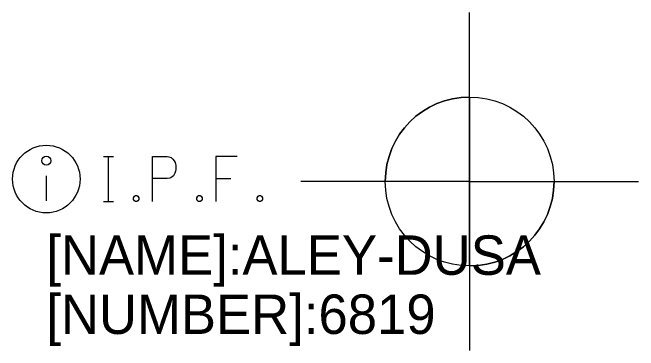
# Model space of a CAD drawing. Extents: x 1386013 to 1389776, y 604170 to 607009.
# Drawn here: x 1389753.55 to 1389775.79, y 606997.38 to 607009.38 of the extents above; entities that cross this region are included whole.
import ezdxf

# ---------------------------------------------------------------- set-up
doc = ezdxf.new("R2010")
doc.units = 0
for name, color, linetype in [('SC_Scratch1', 7, 'Continuous'), ('SH_Text', 7, 'Continuous'), ('SV_X_Mon_Cells_Found_Text', 7, 'Continuous')]:
    doc.layers.add(name, color=color, linetype=linetype)

msp = doc.modelspace()

# ---------------------------------------------------------------- linework, layer by layer
at = {"layer": 'SC_Scratch1'}
msp.add_line((1389754.745, 607003.58), (1389754.745, 607002.697), dxfattribs=at)
for points in [[(1389756.775, 607004.264), (1389757.128, 607004.264)], [(1389756.952, 607002.664), (1389756.952, 607004.264)], [(1389758.517, 607002.664), (1389758.517, 607004.264), (1389759.046, 607004.264), (1389759.101, 607004.251), (1389759.178, 607004.226), (1389759.212, 607004.201), (1389759.244, 607004.176), (1389759.289, 607004.113), (1389759.322, 607004.05), (1389759.344, 607003.949), (1389759.344, 607003.798), (1389759.333, 607003.747), (1389759.311, 607003.672), (1389759.267, 607003.584), (1389759.222, 607003.546), (1389759.189, 607003.52), (1389759.134, 607003.495), (1389759.046, 607003.483), (1389758.517, 607003.483)], [(1389761.526, 607004.264), (1389760.766, 607004.264), (1389760.766, 607002.664)], [(1389760.766, 607003.483), (1389761.306, 607003.483)], [(1389757.911, 607002.878), (1389757.966, 607002.878), (1389757.999, 607002.853), (1389758.032, 607002.802), (1389758.032, 607002.739), (1389757.999, 607002.689), (1389757.966, 607002.664), (1389757.911, 607002.664), (1389757.878, 607002.689), (1389757.845, 607002.739), (1389757.845, 607002.802), (1389757.878, 607002.853), (1389757.911, 607002.878)], [(1389760.159, 607002.878), (1389760.215, 607002.878), (1389760.248, 607002.853), (1389760.281, 607002.802), (1389760.281, 607002.739), (1389760.248, 607002.689), (1389760.215, 607002.664), (1389760.159, 607002.664), (1389760.126, 607002.689), (1389760.093, 607002.739), (1389760.093, 607002.802), (1389760.126, 607002.853), (1389760.159, 607002.878)], [(1389762.309, 607002.878), (1389762.364, 607002.878), (1389762.397, 607002.853), (1389762.43, 607002.802), (1389762.43, 607002.739), (1389762.397, 607002.689), (1389762.364, 607002.664), (1389762.309, 607002.664), (1389762.276, 607002.689), (1389762.243, 607002.739), (1389762.243, 607002.802), (1389762.276, 607002.853), (1389762.309, 607002.878)], [(1389756.775, 607002.664), (1389757.128, 607002.664)]]:
    msp.add_lwpolyline(points, dxfattribs=at)
for centre, radius in [((1389754.745, 607003.464), 1.2), ((1389754.745, 607004.115), 0.16)]:
    msp.add_circle(centre, radius, dxfattribs=at)
at = {"layer": 'SH_Text'}
for p, q in [((1389769.792, 607003.378), (1389769.792, 607009.378)), ((1389769.792, 607006.378), (1389769.792, 607003.378)), ((1389769.792, 607003.378), (1389763.792, 607003.378)), ((1389769.792, 607003.378), (1389766.792, 607003.378)), ((1389769.792, 607003.378), (1389769.792, 606997.378)), ((1389769.792, 607003.378), (1389775.792, 607003.378)), ((1389769.792, 607000.378), (1389769.792, 607003.378)), ((1389769.792, 607003.378), (1389772.792, 607003.378))]:
    msp.add_line(p, q, dxfattribs=at)
msp.add_circle((1389769.792, 607003.378), 3, dxfattribs=at)
for start, end in [(90, 180), (270, 360)]:
    msp.add_arc((1389769.792, 607003.378), 3, start, end, dxfattribs=at)

# ---------------------------------------------------------------- texts
at = {"layer": 'SV_X_Mon_Cells_Found_Text'}
for s, p in [('[NAME]:ALEY-DUSA', (1389754.745, 607000.064)), ('[NUMBER]:6819', (1389754.745, 606997.964))]:
    msp.add_text(s, height=1.4, dxfattribs=at).set_placement(p)

doc.saveas('drawing.dxf')
